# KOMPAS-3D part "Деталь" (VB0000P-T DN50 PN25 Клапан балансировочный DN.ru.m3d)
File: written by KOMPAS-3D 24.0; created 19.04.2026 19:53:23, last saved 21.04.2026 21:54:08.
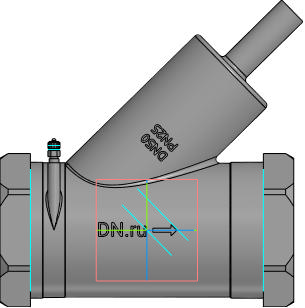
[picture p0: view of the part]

Document properties: Автор: mrdid; Полное имя файла: C:\Работа\VB0000P-T DN X PN 25 Клапан балансировочный DN.ru\DN50\исходные материалы\VB0000P-T DN50 PN25 Клапан балансировочный DN.ru.m3d

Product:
- Body: Тело 1  | qty 1
    Масса: 2.661241
- Body: Тело 2  | qty 1
    Масса: 2.661241
- Body: Тело 3  | qty 1
    Масса: 2.661241
- Body: Тело 4  | qty 1
    Масса: 2.661241
- Body: Тело 5  | qty 1
    Масса: 2.661241
- Body: Тело 6  | qty 1
    Масса: 2.661241
- Body: Тело 7  | qty 1
    Масса: 2.661241
- Body: Тело 8  | qty 1
    Масса: 2.661241
- Body: Тело 9  | qty 1
    Масса: 2.661241
- Body: Тело 10  | qty 1
    Масса: 2.661241
- Part/product: Деталь
    Масса: 0.00084
    Раздел спецификации: Прочие изделия
    Примечание: D080-01177

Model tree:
1. Эскиз:1
2. Элемент вращения:1
     Угол 1 = 360
3. Фаска:1  (with: Ребро.Элемент вращения:1)
     Угол = 45; Длина 1 = 3; Длина 2 = 3
4. Фаска:2  (with: Ребро.Элемент вращения:1)
     Угол = 45; Длина 1 = 2; Длина 2 = 2
5. Фаска:3  (with: Ребро.Элемент вращения:1)
     Угол = 45; Длина 1 = 1; Длина 2 = 1
6. Фаска:4  (with: Ребро.Элемент вращения:1)
     Угол = 30; Длина 1 = 4; Длина 2 = 2.3094
7. Смещенная плоскость:1  (with: Грань.Элемент вращения:1)
     Расстояние = 15
8. Эскиз:2
9. Элемент выдавливания:1  (with: Грань.Фаска:4)
     Расстояние 1 = 76.4802
10. Эскиз:3
11. Элемент выдавливания:2  (with: Грань.Фаска:4)
12. Смещенная плоскость:2  (with: Грань.Элемент вращения:1)
     Расстояние = 15
13. Эскиз:4  (with: Ребро.Фаска:4)
14. Элемент выдавливания:3  (with: Грань.Фаска:4)
15. Эскиз:5
16. Элемент выдавливания:4  (with: Грань.Фаска:4)
     Расстояние 2 = 79.4802
17. Фаска:5  (with: Ребро.Элемент выдавливания:2, Ребро.Элемент выдавливания:4)
     Угол = 45; Длина 1 = 2; Длина 2 = 2
18. Плоскость под углом:1
     Угол = 45.5
19. Смещенная плоскость:3
     Расстояние = 11
20. Касательная плоскость:1  (with: Грань.Элемент вращения:1)
21. Эскиз:6  (with: Ребро.Фаска:3)
22. Элемент выдавливания:5  (with: Грань.Элемент вращения:1)
     Расстояние 1 = 8.86186; Расстояние 2 = 75
23. Эскиз:7  (with: Грань.Элемент вращения:1)
24. Элемент выдавливания:6  (with: Грань.Элемент вращения:1)
25. Эскиз:8  (with: Грань.Элемент выдавливания:6, Ребро.Элемент выдавливания:6)
26. Элемент выдавливания:7
     Расстояние 1 = 2
27. Эскиз:9  (with: Грань.Элемент выдавливания:7, Ребро.Элемент выдавливания:7)
28. Элемент выдавливания:8
     Расстояние 1 = 1
29. Эскиз:10  (with: Грань.Элемент выдавливания:8, Ребро.Элемент выдавливания:6)
30. Элемент выдавливания:10
     Расстояние 1 = 3
31. Эскиз:11  (with: Грань.Элемент выдавливания:10, Ребро.Элемент выдавливания:6)
32. Элемент выдавливания:11
     Расстояние 1 = 1
33. Эскиз:12  (with: Грань.Элемент выдавливания:11, Ребро.Элемент выдавливания:6)
34. Элемент выдавливания:12
     Расстояние 1 = 3
35. Эскиз:13  (with: Грань.Элемент выдавливания:12, Ребро.Элемент выдавливания:7)
36. Элемент выдавливания:13
     Расстояние 1 = 2
37. Скругление:1  (with: Ребро.Элемент выдавливания:13)
     Радиус = 1
38. Средняя плоскость:2  (with: Грань.Элемент выдавливания:12, Грань.Элемент выдавливания:10)
39. Эскиз:14  (with: Ребро.Элемент выдавливания:7)
40. Элемент выдавливания:14
     Расстояние 1 = 0.5
41. Средняя плоскость:3  (with: Грань.Элемент выдавливания:12)
42. Эскиз:15  (with: Вершина.Элемент выдавливания:14, Ребро.Элемент выдавливания:14)
43. Эскиз:16  (with: Грань.Элемент выдавливания:12, Ребро.Элемент выдавливания:7)
44. Элемент выдавливания:15
     Расстояние 1 = 0.5
45. Элемент выдавливания:16  (with: Грань.Элемент выдавливания:15, Грань.Элемент выдавливания:14)
     Расстояние 1 = 1.5; Расстояние 2 = 1.75
46. Скругление:2  (with: Ребро.Элемент выдавливания:14, Ребро.Элемент выдавливания:15, Ребро.Элемент выдавливания:16)
     Радиус = 1
47. Зеркальный массив:1
48. Экземпляр ( 1 )
49. Экземпляр ( 2 )  (with: Элемент выдавливания:15, Элемент выдавливания:16, Элемент выдавливания:14, Скругление:2)
50. Скругление:3  (with: Ребро.Элемент выдавливания:5)
     Радиус = 2
51. Скругление:4  (with: Ребро.Элемент выдавливания:6)
     Радиус = 1
52. Эскиз:17  (with: Грань.Элемент выдавливания:5, Ребро.Элемент выдавливания:5)
53. Элемент выдавливания:17
     Расстояние 1 = 41
54. Скругление:5  (with: Ребро.Элемент выдавливания:17, Ребро.Элемент выдавливания:5)
     Радиус = 2
55. Скругление:6  (with: Ребро.Элемент выдавливания:2, Ребро.Элемент выдавливания:4)
     Радиус = 1
56. Эскиз:19  (with: Грань.Элемент выдавливания:5)
57. Элемент выдавливания:19  (with: Грань.Элемент выдавливания:5)
     Расстояние 1 = 25.196; Смещение 1 = 0.2
58. Эскиз:20
59. Элемент выдавливания:20  (with: Грань.Элемент вращения:1)
     Расстояние 1 = 33.2; Смещение 1 = 0.2; Расстояние 2 = 33.2; Смещение 2 = 0.2
60. Эскиз:21
61. Элемент выдавливания:21  (with: Грань.Элемент вращения:1)
     Расстояние 1 = 33.1986; Смещение 1 = 0.2
62. Эскиз:22  (with: Ребро.Фаска:2)
63. Элемент выдавливания:22
     Расстояние 1 = 72.5; Расстояние 2 = 77.0911

Expressions: 1/2*25.4
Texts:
  Линейный размер с обрывом
  GOST 26.020 Pr3
  var3D
  Ds-1
  Ds-2
  Ds-4
  Gn+S+5
  Dn+0.5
